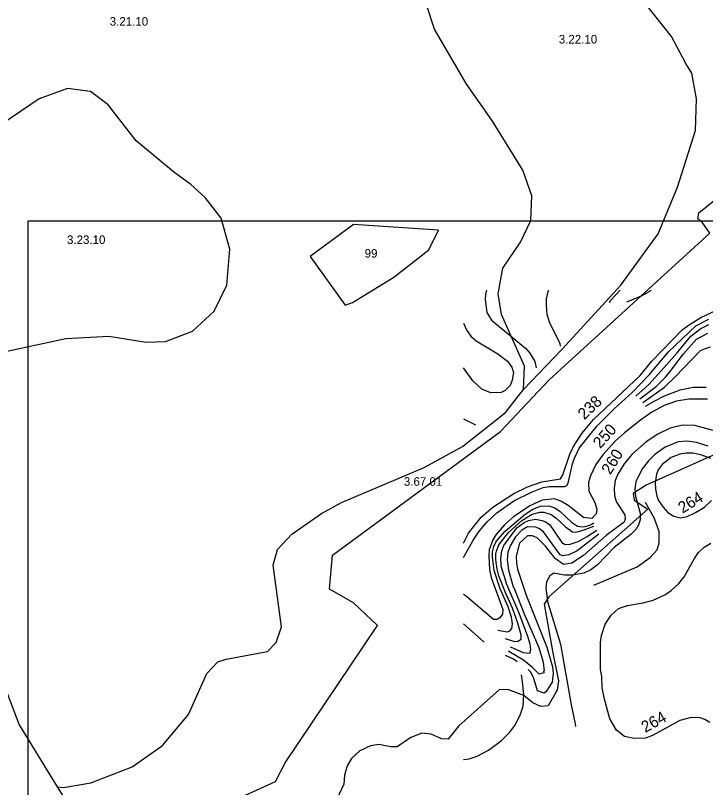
# Model space of a CAD drawing. Extents: x -662500 to -653478, y -1056827 to -1049993.
# Drawn here: x -661983 to -661381, y -1051447 to -1050774 of the extents above; entities that cross this region are included whole.
import ezdxf

# ---------------------------------------------------------------- set-up
doc = ezdxf.new("R2010")
doc.units = 0
for name, color, linetype in [('Vrstva 24', 7, 'Continuous'), ('Vrstva 7', 7, 'Continuous'), ('Vrstva 9', 7, 'Continuous')]:
    doc.layers.add(name, color=color, linetype=linetype)

msp = doc.modelspace()

# ---------------------------------------------------------------- linework, layer by layer
at = {"layer": 'Vrstva 24'}
for points in [[(-661540, -1051100), (-661539, -1051079.5), (-661559, -1051034.5), (-661562, -1051016.5), (-661558, -1050994), (-661542.5, -1050971.5), (-661533.5, -1050952.5), (-661532.5, -1050931), (-661540.5, -1050908.5), (-661567, -1050866), (-661590, -1050833), (-661617.5, -1050785.5), (-661624.5, -1050764.5), (-661629, -1050719.5), (-661632, -1050692), (-661638, -1050674.5), (-661648, -1050652), (-661661, -1050629), (-661670, -1050620.5), (-661686, -1050593.5), (-661692, -1050559)], [(-661540, -1051100), (-661506.5, -1051065), (-661455, -1051009), (-661422.5, -1050964), (-661405.5, -1050923.5), (-661390, -1050874), (-661389, -1050846.5), (-661393, -1050824), (-661398.5, -1050815.5), (-661411, -1050792), (-661463.5, -1050725.5), (-661505, -1050677), (-661536.5, -1050649), (-661556.5, -1050622), (-661579.59, -1050581.23)], [(-662100, -1051077.5), (-662000, -1051068.5), (-661939, -1051055.5), (-661901.5, -1051053.5), (-661869, -1051058.5), (-661852, -1051058), (-661828.5, -1051049), (-661809.5, -1051031.5), (-661798.5, -1051009), (-661796, -1050977.5), (-661803.5, -1050950.5), (-661817.5, -1050932.5), (-661830, -1050921), (-661845, -1050910), (-661877.5, -1050883), (-661902, -1050851.5), (-661917.5, -1050840), (-661937.5, -1050837.5), (-661962, -1050846.5), (-662003, -1050874), (-662041.5, -1050914.5), (-662064, -1050946), (-662099.5, -1051013.5), (-662116.5, -1051030)], [(-661782.37, -1051453.8), (-661756.21, -1051441.68), (-661747.67, -1051425.44), (-661667.23, -1051305.69), (-661688, -1051286), (-661709, -1051274), (-661706.5, -1051244.5), (-661560, -1051136.5), (-661517.5, -1051091.5), (-661377.5, -1050963.5), (-661384, -1050954), (-661387.79, -1050951.02), (-661386.97, -1050945.78), (-661365.77, -1050928.71)], [(-661946.5, -1051446.5), (-661941, -1051447), (-661917, -1051443), (-661881, -1051429), (-661854.5, -1051410.5), (-661832, -1051383.5), (-661816, -1051347.5), (-661806.5, -1051337.5), (-661799, -1051335), (-661763, -1051328.5), (-661755.5, -1051320.5), (-661751, -1051307), (-661758, -1051253), (-661754.5, -1051239.5), (-661742, -1051226), (-661716, -1051208), (-661698.5, -1051198.5), (-661626.5, -1051168), (-661593, -1051149.5), (-661555.5, -1051120), (-661540, -1051100)], [(-661359.57, -1051150.64), (-661432.95, -1051183.41)], [(-662040, -1051177), (-661998, -1051345), (-661979.5, -1051392.5), (-661946.5, -1051446.5)], [(-661432.95, -1051183.41), (-661444.24, -1051190.57), (-661443.41, -1051196.35), (-661431.57, -1051204.33), (-661517.9, -1051280.61), (-661521.75, -1051287.21), (-661514.73, -1051328.24), (-661509.5, -1051354.12), (-661510.6, -1051362.11), (-661518.31, -1051375.88), (-661524.92, -1051376.43), (-661531.8, -1051373.12), (-661539.51, -1051366.79), (-661553.55, -1051361.56), (-661560.99, -1051361.83), (-661596.37, -1051393.22), (-661605.46, -1051404.79), (-661611.24, -1051404.51), (-661620.33, -1051400.66), (-661628.59, -1051399.56), (-661638.22, -1051403.41), (-661650.06, -1051411.67), (-661655.57, -1051411.67), (-661666.03, -1051409.47), (-661673.19, -1051410.84), (-661682.55, -1051414.98), (-661689.99, -1051421.86), (-661693.57, -1051428.19), (-661696.05, -1051436.18), (-661696.6, -1051444.16), (-661702.93, -1051457.93)], [(-661946.5, -1051446.5), (-661906, -1051511), (-661893.5, -1051524.5), (-661879, -1051532), (-661862, -1051529.5), (-661849, -1051522)]]:
    msp.add_lwpolyline(points, dxfattribs=at)
msp.add_lwpolyline([(-661653, -1051002), (-661622.5, -1050978), (-661614, -1050961), (-661688, -1050956), (-661726, -1050984), (-661695.5, -1051026.5), (-661689, -1051024)], close=True, dxfattribs=at)
at = {"layer": 'Vrstva 7'}
for p, q in [((-661573, -1051016.87), (-661573.42, -1051021.4)), ((-661572.22, -1051013.4), (-661573, -1051016.87)), ((-661519.71, -1051020.83), (-661518.15, -1051013.46)), ((-661518.15, -1051013.46), (-661518.13, -1051013.4)), ((-661463.73, -1051021.97), (-661455.71, -1051013.4)), ((-661449.92, -1051023.49), (-661437, -1051018.1)), ((-661437, -1051018.1), (-661428.38, -1051013.4)), ((-661573.42, -1051021.4), (-661571.72, -1051032.74)), ((-661519.99, -1051026.5), (-661519.71, -1051020.83)), ((-661519.29, -1051034.44), (-661519.99, -1051026.5)), ((-661464.81, -1051024.05), (-661463.73, -1051021.97)), ((-661571.72, -1051032.74), (-661567.75, -1051039.54)), ((-661385.41, -1051037.13), (-661372.13, -1051031.03)), ((-661567.75, -1051039.54), (-661538.28, -1051063.92)), ((-661517.02, -1051042.09), (-661519.29, -1051034.44)), ((-661394.74, -1051042.87), (-661385.41, -1051037.13)), ((-661389.71, -1051044.31), (-661378.23, -1051038.56)), ((-661592.25, -1051042.15), (-661589.44, -1051048.33)), ((-661508, -1051059.65), (-661517.02, -1051042.09)), ((-661413.4, -1051066.92), (-661389.71, -1051044.31)), ((-661401.55, -1051047.9), (-661394.74, -1051042.87)), ((-661385.41, -1051046.82), (-661378.23, -1051043.23)), ((-661589.44, -1051048.33), (-661585.75, -1051053.29)), ((-661585.75, -1051053.29), (-661581.08, -1051057.54)), ((-661428.16, -1051075.32), (-661401.55, -1051047.9)), ((-661406.22, -1051068.36), (-661394.02, -1051053.28)), ((-661394.02, -1051053.28), (-661385.41, -1051046.82)), ((-661389, -1051056.15), (-661379.31, -1051050.77)), ((-661581.08, -1051057.54), (-661562.23, -1051068.88)), ((-661507.57, -1051062.25), (-661508, -1051059.65)), ((-661400.48, -1051068.72), (-661389, -1051056.15)), ((-661538.28, -1051063.92), (-661534.45, -1051068.31)), ((-661430.43, -1051087.16), (-661413.4, -1051066.92)), ((-661407.56, -1051088.83), (-661385.46, -1051066.02)), ((-661385.46, -1051066.02), (-661381.26, -1051064.2)), ((-661381.26, -1051064.2), (-661377, -1051062.64)), ((-661562.23, -1051068.88), (-661553.86, -1051075.25)), ((-661534.45, -1051068.31), (-661530.06, -1051075.54)), ((-661417.25, -1051080.64), (-661406.22, -1051068.36)), ((-661411.02, -1051083.19), (-661400.48, -1051068.72)), ((-661553.86, -1051075.25), (-661550.18, -1051080.35)), ((-661550.18, -1051080.35), (-661548.59, -1051085.23)), ((-661530.06, -1051075.54), (-661528.86, -1051080.92)), ((-661438.22, -1051087.72), (-661428.16, -1051075.32)), ((-661584.19, -1051092.4), (-661592.25, -1051081)), ((-661548.59, -1051085.23), (-661549.67, -1051091.69)), ((-661444.74, -1051102.18), (-661430.43, -1051087.16)), ((-661430.57, -1051095.66), (-661417.25, -1051080.64)), ((-661415.97, -1051089.14), (-661411.02, -1051083.19)), ((-661576.11, -1051099.49), (-661584.19, -1051092.4)), ((-661549.67, -1051091.69), (-661551.46, -1051096.36)), ((-661478.9, -1051126.13), (-661438.22, -1051087.72)), ((-661424.34, -1051097.36), (-661415.97, -1051089.14)), ((-661416.97, -1051097.79), (-661407.56, -1051088.83)), ((-661568.32, -1051102.89), (-661576.11, -1051099.49)), ((-661555.77, -1051100.66), (-661559.36, -1051102.46)), ((-661551.46, -1051096.36), (-661555.77, -1051100.66)), ((-661442.05, -1051105.72), (-661430.57, -1051095.66)), ((-661438.37, -1051108.13), (-661424.34, -1051097.36)), ((-661435.82, -1051111.11), (-661416.97, -1051097.79)), ((-661416.97, -1051105.44), (-661403.36, -1051100.2)), ((-661403.36, -1051100.2), (-661392.03, -1051097.93)), ((-661392.03, -1051097.93), (-661380.69, -1051097.79)), ((-661559.36, -1051102.46), (-661568.32, -1051102.89)), ((-661460.9, -1051116.78), (-661444.74, -1051102.18)), ((-661426.04, -1051109.97), (-661416.97, -1051105.44)), ((-661433.55, -1051114.45), (-661426.04, -1051109.97)), ((-661417.25, -1051113.8), (-661428.02, -1051119.61)), ((-661406.48, -1051109.97), (-661417.25, -1051113.8)), ((-661395.71, -1051108.27), (-661406.48, -1051109.97)), ((-661379.55, -1051108.42), (-661395.71, -1051108.27)), ((-661475.78, -1051131.66), (-661460.9, -1051116.78)), ((-661428.02, -1051119.61), (-661437.94, -1051126.55)), ((-661592.25, -1051125.5), (-661581.6, -1051130.82)), ((-661489.1, -1051138.18), (-661478.9, -1051126.13)), ((-661437.94, -1051126.55), (-661451.97, -1051137.61)), ((-661491.23, -1051151.21), (-661475.78, -1051131.66)), ((-661412.15, -1051133.78), (-661422.92, -1051138.74)), ((-661401.38, -1051131.09), (-661412.15, -1051133.78)), ((-661390.61, -1051131.23), (-661401.38, -1051131.09)), ((-661374.45, -1051135.62), (-661390.61, -1051131.23)), ((-661496.19, -1051149.51), (-661489.1, -1051138.18)), ((-661451.97, -1051137.61), (-661459.91, -1051144.98)), ((-661422.92, -1051138.74), (-661432.84, -1051145.69)), ((-661459.91, -1051144.98), (-661470.82, -1051157.02)), ((-661432.84, -1051145.69), (-661445.45, -1051156.74)), ((-661405.06, -1051145.69), (-661416.4, -1051150.22)), ((-661397.13, -1051144.98), (-661405.06, -1051145.69)), ((-661389.19, -1051146.11), (-661397.13, -1051144.98)), ((-661378.99, -1051149.37), (-661389.19, -1051146.11)), ((-661499.45, -1051156.31), (-661496.19, -1051149.51)), ((-661495.48, -1051159.86), (-661491.23, -1051151.21)), ((-661416.4, -1051150.22), (-661425.33, -1051156.6)), ((-661505.68, -1051174.31), (-661499.45, -1051156.31)), ((-661497.18, -1051164.82), (-661495.48, -1051159.86)), ((-661470.82, -1051157.02), (-661476.77, -1051165.39)), ((-661445.45, -1051156.74), (-661452.11, -1051164.68)), ((-661425.33, -1051156.6), (-661431, -1051162.12)), ((-661411.02, -1051159.15), (-661419.09, -1051165.24)), ((-661403.65, -1051156.31), (-661411.02, -1051159.15)), ((-661397.98, -1051155.47), (-661403.65, -1051156.31)), ((-661392.31, -1051155.46), (-661397.98, -1051155.47)), ((-661385.22, -1051156.88), (-661392.31, -1051155.46)), ((-661376.72, -1051160), (-661385.22, -1051156.88)), ((-661500.86, -1051181.54), (-661497.18, -1051164.82)), ((-661476.77, -1051165.39), (-661481.59, -1051175.16)), ((-661452.11, -1051164.68), (-661457.64, -1051173.75)), ((-661431, -1051162.12), (-661436.52, -1051169.21)), ((-661419.09, -1051165.24), (-661422.49, -1051170.06)), ((-661507.67, -1051177.86), (-661505.68, -1051174.31)), ((-661457.64, -1051173.75), (-661460.05, -1051179.27)), ((-661436.52, -1051169.21), (-661442.05, -1051180.55)), ((-661424.05, -1051173.89), (-661425.19, -1051181.26)), ((-661422.49, -1051170.06), (-661424.05, -1051173.89)), ((-661536.29, -1051184.94), (-661523.82, -1051180.55)), ((-661523.82, -1051180.55), (-661507.67, -1051177.86)), ((-661481.59, -1051175.16), (-661483.15, -1051180.97)), ((-661483.15, -1051180.97), (-661482.86, -1051188.63)), ((-661460.05, -1051179.27), (-661460.83, -1051185.87)), ((-661442.05, -1051180.55), (-661442.76, -1051186.64)), ((-661425.19, -1051181.26), (-661424.9, -1051186.93)), ((-661548.2, -1051190.75), (-661536.29, -1051184.94)), ((-661532.89, -1051189.33), (-661522.69, -1051185.51)), ((-661522.69, -1051185.51), (-661517.59, -1051184.38)), ((-661517.59, -1051184.38), (-661503.98, -1051184.52)), ((-661503.98, -1051184.52), (-661502.14, -1051183.52)), ((-661502.14, -1051183.52), (-661500.86, -1051181.54)), ((-661460.83, -1051185.87), (-661460.47, -1051192.59)), ((-661442.76, -1051186.64), (-661442.19, -1051193.16)), ((-661424.9, -1051186.93), (-661423.77, -1051192.88)), ((-661566.62, -1051202.51), (-661548.2, -1051190.75)), ((-661548.2, -1051197.13), (-661532.89, -1051189.33)), ((-661482.86, -1051188.63), (-661477.76, -1051198.55)), ((-661460.47, -1051192.59), (-661458.92, -1051198.26)), ((-661442.19, -1051193.16), (-661438.08, -1051207.9)), ((-661423.77, -1051192.88), (-661422.07, -1051196.85)), ((-661563.08, -1051207.62), (-661548.2, -1051197.13)), ((-661534.31, -1051201.24), (-661548.76, -1051211.02)), ((-661523.54, -1051196.42), (-661534.31, -1051201.24)), ((-661531.76, -1051204.22), (-661524.95, -1051201.66)), ((-661524.95, -1051201.66), (-661517.87, -1051201.52)), ((-661512.77, -1051195.29), (-661523.54, -1051196.42)), ((-661517.87, -1051201.52), (-661512.63, -1051203.22)), ((-661507.38, -1051197.41), (-661512.77, -1051195.29)), ((-661501.01, -1051200.96), (-661507.38, -1051197.41)), ((-661487.54, -1051211.58), (-661501.01, -1051200.96)), ((-661477.76, -1051198.55), (-661475.92, -1051204.22)), ((-661458.92, -1051198.26), (-661451.55, -1051209.32)), ((-661425.9, -1051211.87), (-661433.41, -1051198.41)), ((-661422.07, -1051196.85), (-661418.1, -1051202.66)), ((-661382.1, -1051202.51), (-661375.87, -1051196.85)), ((-661576.68, -1051211.3), (-661566.62, -1051202.51)), ((-661571.44, -1051215.27), (-661563.08, -1051207.62)), ((-661538.56, -1051208.61), (-661531.76, -1051204.22)), ((-661532.33, -1051208.75), (-661525.52, -1051206.77)), ((-661525.52, -1051206.77), (-661522.12, -1051206.77)), ((-661522.12, -1051206.77), (-661515.74, -1051208.89)), ((-661512.63, -1051203.22), (-661507.95, -1051206.2)), ((-661507.95, -1051206.2), (-661498.03, -1051215.55)), ((-661476.49, -1051208.32), (-661480.46, -1051212.29)), ((-661475.92, -1051204.22), (-661476.49, -1051208.32)), ((-661438.08, -1051207.9), (-661438.22, -1051213.57)), ((-661418.1, -1051202.66), (-661413.99, -1051207.33)), ((-661413.99, -1051207.33), (-661408.89, -1051210.31)), ((-661397.13, -1051210.59), (-661390.04, -1051207.33)), ((-661390.04, -1051207.33), (-661382.1, -1051202.51)), ((-661587.74, -1051225.19), (-661576.68, -1051211.3)), ((-661548.76, -1051211.02), (-661556.56, -1051217.96)), ((-661555.85, -1051223.49), (-661538.56, -1051208.61)), ((-661552.86, -1051224.52), (-661541.25, -1051214.14)), ((-661541.25, -1051214.14), (-661532.33, -1051208.75)), ((-661539.41, -1051215.98), (-661535.44, -1051214.28)), ((-661535.44, -1051214.28), (-661529.49, -1051213)), ((-661529.49, -1051213), (-661523.54, -1051214.14)), ((-661523.54, -1051214.14), (-661520.14, -1051215.69)), ((-661515.74, -1051208.89), (-661511.78, -1051211.73)), ((-661511.78, -1051211.73), (-661503.41, -1051219.8)), ((-661480.46, -1051212.29), (-661487.54, -1051211.58)), ((-661451.12, -1051212.72), (-661452.26, -1051215.55)), ((-661451.55, -1051209.32), (-661451.12, -1051212.72)), ((-661438.22, -1051213.57), (-661439.64, -1051217.82)), ((-661421.5, -1051223.77), (-661425.9, -1051211.87)), ((-661408.89, -1051210.31), (-661402.94, -1051211.87)), ((-661402.94, -1051211.87), (-661397.13, -1051210.59)), ((-661578.38, -1051223.21), (-661571.44, -1051215.27)), ((-661556.56, -1051217.96), (-661563.97, -1051226.57)), ((-661557.12, -1051235.96), (-661545.79, -1051220.6)), ((-661545.79, -1051220.6), (-661539.41, -1051215.98)), ((-661536.29, -1051219.66), (-661541.39, -1051222.64)), ((-661529.21, -1051219.95), (-661536.29, -1051219.66)), ((-661525.81, -1051221.36), (-661529.21, -1051219.95)), ((-661522.4, -1051224.2), (-661525.81, -1051221.36)), ((-661520.14, -1051215.69), (-661516.88, -1051218.1)), ((-661516.88, -1051218.1), (-661506.53, -1051233.41)), ((-661503.41, -1051219.8), (-661497.32, -1051224.05)), ((-661498.03, -1051215.55), (-661492.79, -1051219.09)), ((-661492.79, -1051219.09), (-661488.63, -1051219.61)), ((-661488.63, -1051219.61), (-661484.76, -1051219.04)), ((-661487.81, -1051222.69), (-661478.44, -1051219.04)), ((-661484.76, -1051219.04), (-661480.89, -1051217.56)), ((-661480.89, -1051217.56), (-661478.62, -1051216.19)), ((-661452.26, -1051215.55), (-661467.84, -1051227.17)), ((-661439.64, -1051217.82), (-661442.05, -1051222.07)), ((-661592.25, -1051233.88), (-661587.74, -1051225.19)), ((-661584.19, -1051231.85), (-661578.38, -1051223.21)), ((-661563.97, -1051226.57), (-661566.7, -1051231.13)), ((-661562.33, -1051230.69), (-661555.85, -1051223.49)), ((-661561.38, -1051235.39), (-661552.86, -1051224.52)), ((-661546.92, -1051228.31), (-661551.6, -1051236.24)), ((-661541.39, -1051222.64), (-661546.92, -1051228.31)), ((-661536.29, -1051227.46), (-661543.24, -1051233.83)), ((-661532.04, -1051227.46), (-661536.29, -1051227.46)), ((-661527.93, -1051229.3), (-661532.04, -1051227.46)), ((-661507.81, -1051244.04), (-661522.4, -1051224.2)), ((-661497.32, -1051224.05), (-661494.34, -1051224.48)), ((-661494.34, -1051224.48), (-661487.81, -1051222.69)), ((-661474.36, -1051226.04), (-661493.07, -1051240.49)), ((-661492.36, -1051232.42), (-661485.06, -1051228.45)), ((-661467.84, -1051227.17), (-661487.54, -1051244.75)), ((-661485.06, -1051228.45), (-661476.06, -1051222.5)), ((-661446.44, -1051226.32), (-661460.76, -1051237.66)), ((-661442.05, -1051222.07), (-661446.44, -1051226.32)), ((-661421.64, -1051233.69), (-661421.5, -1051223.77)), ((-661592.25, -1051246.48), (-661584.19, -1051231.85)), ((-661566.7, -1051231.13), (-661569.72, -1051239.63)), ((-661565.76, -1051236.89), (-661564.03, -1051233.15)), ((-661564.03, -1051233.15), (-661562.33, -1051230.69)), ((-661543.24, -1051233.83), (-661546.21, -1051245.31)), ((-661520.7, -1051236.53), (-661527.93, -1051229.3)), ((-661506.53, -1051233.41), (-661503.7, -1051234.97)), ((-661503.7, -1051234.97), (-661499.16, -1051234.83)), ((-661499.16, -1051234.83), (-661492.36, -1051232.42)), ((-661423.34, -1051239.64), (-661421.64, -1051233.69)), ((-661382.25, -1051237.38), (-661376.44, -1051233.83)), ((-661569.72, -1051239.63), (-661570.17, -1051244.88)), ((-661567.05, -1051241.49), (-661565.76, -1051236.89)), ((-661566.91, -1051246.25), (-661567.05, -1051241.49)), ((-661564.03, -1051243.22), (-661563.36, -1051240.78)), ((-661563.36, -1051240.78), (-661561.38, -1051235.39)), ((-661559.68, -1051247.3), (-661558.68, -1051240.5)), ((-661558.68, -1051240.5), (-661557.12, -1051235.96)), ((-661551.6, -1051236.24), (-661553.44, -1051242.2)), ((-661512.2, -1051247.3), (-661520.7, -1051236.53)), ((-661493.07, -1051240.49), (-661500.3, -1051244.18)), ((-661460.76, -1051237.66), (-661475.5, -1051252.82)), ((-661429.44, -1051246.59), (-661423.34, -1051239.64)), ((-661387.35, -1051242.2), (-661382.25, -1051237.38)), ((-661570.17, -1051244.88), (-661569.55, -1051256.91)), ((-661566.36, -1051250.74), (-661566.91, -1051246.25)), ((-661563.93, -1051248.43), (-661564.03, -1051243.22)), ((-661562.79, -1051256.65), (-661563.93, -1051248.43)), ((-661559.25, -1051254.1), (-661559.68, -1051247.3)), ((-661553.44, -1051242.2), (-661554.01, -1051248.43)), ((-661554.01, -1051248.43), (-661553.02, -1051257.5)), ((-661546.21, -1051245.31), (-661546.07, -1051250.98)), ((-661505.11, -1051252.68), (-661512.2, -1051247.3)), ((-661505.68, -1051244.89), (-661507.81, -1051244.04)), ((-661500.3, -1051244.18), (-661505.68, -1051244.89)), ((-661487.54, -1051244.75), (-661497.75, -1051251.27)), ((-661440.92, -1051254.67), (-661429.44, -1051246.59)), ((-661399.96, -1051263.45), (-661390.89, -1051247.3)), ((-661390.89, -1051247.3), (-661387.35, -1051242.2)), ((-661565.49, -1051257.78), (-661566.36, -1051250.74)), ((-661554.43, -1051269.97), (-661559.25, -1051254.1)), ((-661546.07, -1051250.98), (-661545.08, -1051256.65)), ((-661497.75, -1051251.27), (-661505.11, -1051252.68)), ((-661475.5, -1051252.82), (-661481.31, -1051257.22)), ((-661478.61, -1051270.54), (-661440.92, -1051254.67)), ((-661569.55, -1051256.91), (-661568.18, -1051264.02)), ((-661560.24, -1051273.66), (-661565.49, -1051257.78)), ((-661561.38, -1051262.32), (-661562.79, -1051256.65)), ((-661553.02, -1051257.5), (-661548.91, -1051272.1)), ((-661545.08, -1051256.65), (-661537.43, -1051279.32)), ((-661513.48, -1051260.19), (-661517.02, -1051262.46)), ((-661504.27, -1051261.75), (-661513.48, -1051260.19)), ((-661497.18, -1051261.75), (-661504.27, -1051261.75)), ((-661487.26, -1051260.05), (-661497.18, -1051261.75)), ((-661481.31, -1051257.22), (-661487.26, -1051260.05)), ((-661568.18, -1051264.02), (-661557.97, -1051291.94)), ((-661555.99, -1051276.49), (-661561.38, -1051262.32)), ((-661519.99, -1051267.7), (-661520.42, -1051272.81)), ((-661517.02, -1051262.46), (-661519.99, -1051267.7)), ((-661411.02, -1051275.22), (-661404.35, -1051268.98)), ((-661404.35, -1051268.98), (-661399.96, -1051263.45)), ((-661553.3, -1051289.53), (-661560.24, -1051273.66)), ((-661543.8, -1051294.91), (-661554.43, -1051269.97)), ((-661548.91, -1051272.1), (-661548.2, -1051272.52)), ((-661548.2, -1051272.52), (-661539.27, -1051295.48)), ((-661520.42, -1051272.81), (-661519, -1051284.71)), ((-661416.54, -1051278.9), (-661411.02, -1051275.22)), ((-661589.58, -1051280.6), (-661592.25, -1051278.7)), ((-661566.05, -1051300.58), (-661589.58, -1051280.6)), ((-661549.61, -1051290.66), (-661555.99, -1051276.49)), ((-661537.43, -1051279.32), (-661519.43, -1051324.67)), ((-661426.75, -1051283.58), (-661416.54, -1051278.9)), ((-661519, -1051284.71), (-661507.67, -1051322.12)), ((-661456.93, -1051290.95), (-661449.28, -1051288.4)), ((-661449.28, -1051288.4), (-661435.67, -1051286.13)), ((-661435.67, -1051286.13), (-661426.75, -1051283.58)), ((-661558.26, -1051295.91), (-661560.67, -1051299.17)), ((-661557.97, -1051291.94), (-661558.26, -1051295.91)), ((-661550.46, -1051298.6), (-661553.3, -1051289.53)), ((-661544.8, -1051303.7), (-661549.61, -1051290.66)), ((-661536.01, -1051315.32), (-661543.8, -1051294.91)), ((-661539.27, -1051295.48), (-661526.51, -1051324.96)), ((-661463.59, -1051296.61), (-661456.93, -1051290.95)), ((-661562.79, -1051300.44), (-661566.05, -1051300.58)), ((-661560.67, -1051299.17), (-661562.79, -1051300.44)), ((-661549.61, -1051304.27), (-661550.46, -1051298.6)), ((-661468.83, -1051304.55), (-661463.59, -1051296.61)), ((-661574.21, -1051320.43), (-661592.25, -1051304.33)), ((-661551.88, -1051310.36), (-661550.18, -1051308.38)), ((-661550.18, -1051308.38), (-661549.61, -1051304.27)), ((-661541.96, -1051313.9), (-661544.8, -1051303.7)), ((-661471.95, -1051314.47), (-661468.83, -1051304.55)), ((-661562.23, -1051309.94), (-661554.15, -1051311.35)), ((-661554.15, -1051311.35), (-661551.88, -1051310.36)), ((-661541.96, -1051317.73), (-661541.96, -1051313.9)), ((-661534.03, -1051322.12), (-661536.01, -1051315.32)), ((-661472.8, -1051320.42), (-661471.95, -1051314.47)), ((-661555.99, -1051317.02), (-661547.63, -1051319.57)), ((-661547.63, -1051319.57), (-661544.8, -1051319.29)), ((-661544.8, -1051319.29), (-661541.96, -1051317.73)), ((-661533.6, -1051326.66), (-661534.03, -1051322.12)), ((-661507.67, -1051322.12), (-661498.31, -1051374.84)), ((-661472.66, -1051344.23), (-661472.8, -1051320.42)), ((-661552.59, -1051328.36), (-661552.73, -1051327.72)), ((-661540.03, -1051335.99), (-661552.59, -1051328.36)), ((-661551.62, -1051324.35), (-661548.58, -1051325.42)), ((-661548.58, -1051325.42), (-661540.26, -1051329.21)), ((-661540.26, -1051329.21), (-661534.31, -1051329.92)), ((-661534.31, -1051329.92), (-661533.6, -1051326.66)), ((-661526.51, -1051324.96), (-661522.69, -1051337.71)), ((-661519.43, -1051324.67), (-661514.75, -1051341.68)), ((-661548.63, -1051335.23), (-661555.52, -1051331.86)), ((-661545.43, -1051337.32), (-661548.63, -1051335.23)), ((-661531.62, -1051342.67), (-661540.03, -1051335.99)), ((-661526.23, -1051348.34), (-661531.62, -1051342.67)), ((-661522.69, -1051337.71), (-661521.98, -1051345.65)), ((-661514.75, -1051341.68), (-661513.9, -1051347.35)), ((-661540.63, -1051354.89), (-661541.7, -1051348.78)), ((-661533.44, -1051346.35), (-661535.86, -1051344)), ((-661530.77, -1051351.88), (-661533.44, -1051346.35)), ((-661522.26, -1051347.06), (-661526.23, -1051348.34)), ((-661521.98, -1051345.65), (-661522.4, -1051345.65)), ((-661522.4, -1051345.65), (-661522.26, -1051347.06)), ((-661513.9, -1051347.35), (-661514.89, -1051355.28)), ((-661471.67, -1051350.18), (-661472.66, -1051344.23)), ((-661539.69, -1051366.05), (-661540.63, -1051354.89)), ((-661527.65, -1051362.8), (-661530.77, -1051351.88)), ((-661514.89, -1051355.28), (-661520.28, -1051363.36)), ((-661471.24, -1051360.1), (-661471.67, -1051350.18)), ((-661521.98, -1051364.78), (-661527.65, -1051362.8)), ((-661469.4, -1051370.02), (-661471.24, -1051360.1)), ((-661540.26, -1051375.98), (-661539.69, -1051366.05)), ((-661520.28, -1051363.36), (-661521.98, -1051364.78)), ((-661464.73, -1051387.03), (-661469.4, -1051370.02)), ((-661542.67, -1051383.91), (-661540.26, -1051375.98)), ((-661498.31, -1051374.84), (-661494.77, -1051391.56)), ((-661547.49, -1051392.98), (-661542.67, -1051383.91)), ((-661458.77, -1051397.09), (-661464.73, -1051387.03)), ((-661403.65, -1051388.59), (-661427.45, -1051401.77)), ((-661393.73, -1051386.04), (-661403.65, -1051388.59)), ((-661385.79, -1051386.32), (-661393.73, -1051386.04)), ((-661381.82, -1051387.74), (-661385.79, -1051386.32)), ((-661377.57, -1051390.29), (-661381.82, -1051387.74)), ((-661551.88, -1051398.93), (-661547.49, -1051392.98)), ((-661494.77, -1051391.56), (-661494.47, -1051393.94)), ((-661558.97, -1051406.16), (-661551.88, -1051398.93)), ((-661451.97, -1051402.62), (-661458.77, -1051397.09)), ((-661443.33, -1051404.46), (-661451.97, -1051402.62)), ((-661427.45, -1051401.77), (-661433.41, -1051403.89)), ((-661570.31, -1051414.52), (-661558.97, -1051406.16)), ((-661433.41, -1051403.89), (-661443.33, -1051404.46)), ((-661580.22, -1051419.62), (-661570.31, -1051414.52)), ((-661592.25, -1051422.75), (-661587.31, -1051422.18)), ((-661587.31, -1051422.18), (-661580.22, -1051419.62))]:
    msp.add_line(p, q, dxfattribs=at)
at = {"layer": 'Vrstva 9'}
for p in [(-657221.63, -1050952.96), (-661971.63, -1054269.45)]:
    msp.add_line(p, (-661971.63, -1050952.96), dxfattribs=at)

# ---------------------------------------------------------------- texts
at = {"layer": 'Vrstva 24'}
for s, p in [('3.21.10', (-661900.62, -1050782.61)), ('3.22.10', (-661509.12, -1050798.14)), ('3.23.10', (-661937.86, -1050973.01)), ('99', (-661678.36, -1050984.88)), ('3.67.01', (-661644.21, -1051183.89))]:
    msp.add_text(s, height=7.5, dxfattribs=at).set_placement(p)
at = {"layer": 'Vrstva 7'}
for s, rotation, p in [('238', 43.35788, (-661486.88, -1051126.79)), ('250', 47.8278, (-661473.01, -1051151.99)), ('260', 58.64306, (-661464.18, -1051174.87)), ('264', 31.2675, (-661401.28, -1051208.31)), ('264', 28.96871, (-661433.79, -1051399.56))]:
    msp.add_text(s, height=10, rotation=rotation, dxfattribs=at).set_placement(p)

doc.saveas('drawing.dxf')
